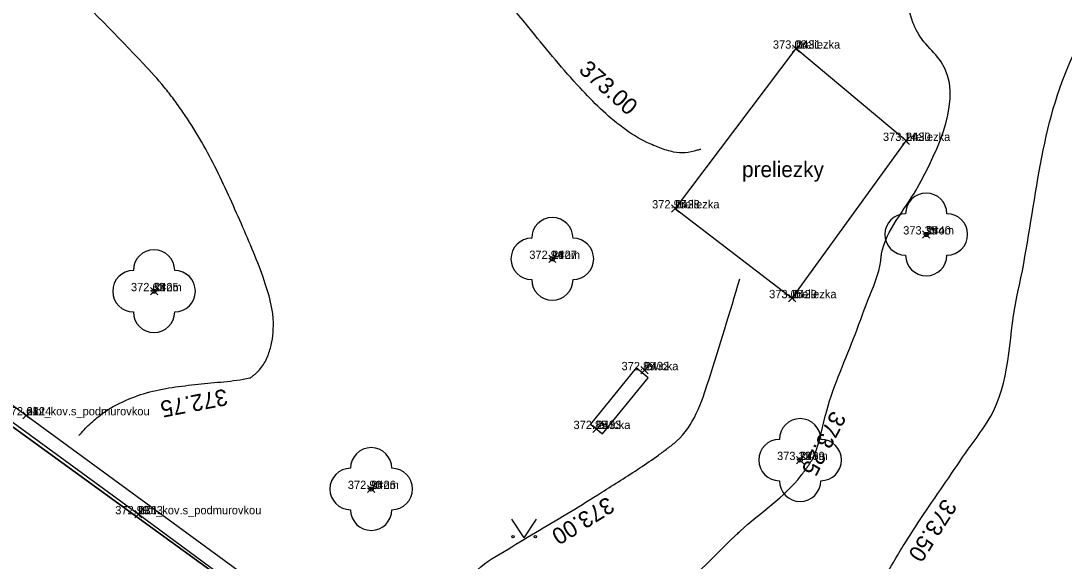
# Model space of a CAD drawing. Extents: x -400488 to -400124, y -1251493 to -1251223.
# Drawn here: x -400314.45 to -400289.23, y -1251383.58 to -1251370.53 of the extents above; entities that cross this region are included whole.
import ezdxf

# ---------------------------------------------------------------- set-up
doc = ezdxf.new("R2010")
doc.units = 0
for name, color, linetype in [('Level 20', 7, 'Continuous'), ('Level 21', 7, 'Continuous'), ('Level 22', 7, 'Continuous'), ('Level 23', 7, 'Continuous'), ('Level 31', 7, 'Continuous'), ('Level 35', 7, 'Continuous'), ('Level 36', 7, 'Continuous'), ('Level 49', 7, 'Continuous'), ('Level 60', 7, 'Continuous'), ('Level 63', 7, 'Continuous')]:
    doc.layers.add(name, color=color, linetype=linetype)

msp = doc.modelspace()

# ---------------------------------------------------------------- linework, layer by layer
at = {"layer": 'Level 20'}
for p, q in [((-400295.798, -1251371.288), (-400295.622, -1251371.112)), ((-400295.622, -1251371.288), (-400295.798, -1251371.112)), ((-400293.138, -1251373.518), (-400292.962, -1251373.342)), ((-400292.962, -1251373.518), (-400293.138, -1251373.342)), ((-400298.718, -1251375.148), (-400298.542, -1251374.972)), ((-400298.542, -1251375.148), (-400298.718, -1251374.972)), ((-400292.648, -1251375.778), (-400292.472, -1251375.602)), ((-400292.472, -1251375.778), (-400292.648, -1251375.602)), ((-400301.688, -1251376.368), (-400301.512, -1251376.192)), ((-400301.512, -1251376.368), (-400301.688, -1251376.192)), ((-400311.318, -1251377.148), (-400311.142, -1251376.972)), ((-400311.142, -1251377.148), (-400311.318, -1251376.972)), ((-400295.888, -1251377.318), (-400295.712, -1251377.142)), ((-400295.712, -1251377.318), (-400295.888, -1251377.142)), ((-400299.458, -1251379.058), (-400299.282, -1251378.882)), ((-400299.282, -1251379.058), (-400299.458, -1251378.882)), ((-400314.398, -1251380.148), (-400314.222, -1251379.972)), ((-400314.222, -1251380.148), (-400314.398, -1251379.972)), ((-400300.618, -1251380.478), (-400300.442, -1251380.302)), ((-400300.442, -1251380.478), (-400300.618, -1251380.302)), ((-400295.698, -1251381.228), (-400295.522, -1251381.052)), ((-400295.522, -1251381.228), (-400295.698, -1251381.052)), ((-400306.068, -1251381.928), (-400305.892, -1251381.752)), ((-400305.892, -1251381.928), (-400306.068, -1251381.752)), ((-400311.698, -1251382.538), (-400311.522, -1251382.362)), ((-400311.522, -1251382.538), (-400311.698, -1251382.362))]:
    msp.add_line(p, q, dxfattribs=at)
at = {"layer": 'Level 31'}
msp.add_lwpolyline([(-400295.71, -1251371.2), (-400298.63, -1251375.06), (-400295.8, -1251377.23), (-400293.05, -1251373.43), (-400295.71, -1251371.2)], dxfattribs=at)
at = {"layer": 'Level 35'}
for points in [[(-400330.938, -1251368.394), (-400330.78, -1251368.19), (-400329.16, -1251369.12), (-400314.31, -1251380.06), (-400302.65, -1251388.59)], [(-400279.37, -1251372.32), (-400292.97, -1251391.4), (-400293.356, -1251391.833), (-400293.82, -1251392.23), (-400294.281, -1251392.435), (-400294.92, -1251392.64), (-400295.666, -1251392.756), (-400296.53, -1251392.79), (-400297.13, -1251392.716), (-400297.73, -1251392.55), (-400298.17, -1251392.329), (-400298.61, -1251392.05), (-400311.61, -1251382.45), (-400320.06, -1251376.29)]]:
    msp.add_lwpolyline(points, dxfattribs=at)
at = {"layer": 'Level 36'}
for q in [(-400302.58, -1251382.572), (-400301.98, -1251382.572)]:
    msp.add_line((-400302.28, -1251383.022), q, dxfattribs=at)
for centre, radius in [((-400292.56, -1251375.69), 0.05), ((-400301.6, -1251376.28), 0.05), ((-400311.23, -1251377.06), 0.05), ((-400295.61, -1251381.14), 0.05), ((-400305.98, -1251381.84), 0.05), ((-400302.55, -1251382.992), 0.03), ((-400302.01, -1251382.992), 0.03)]:
    msp.add_circle(centre, radius, dxfattribs=at)
for centre, start, end in [((-400292.56, -1251375.19), 0, 180), ((-400293.06, -1251375.69), 90, 270), ((-400292.06, -1251375.69), 270, 90), ((-400301.6, -1251375.78), 0, 180), ((-400302.1, -1251376.28), 90, 270), ((-400301.1, -1251376.28), 270, 90), ((-400311.23, -1251376.56), 0, 180), ((-400292.56, -1251376.19), 180, 0), ((-400311.73, -1251377.06), 90, 270), ((-400310.73, -1251377.06), 270, 90), ((-400301.6, -1251376.78), 180, 0), ((-400311.23, -1251377.56), 180, 0), ((-400295.61, -1251380.64), 0, 180), ((-400296.11, -1251381.14), 90, 270), ((-400295.11, -1251381.14), 270, 90), ((-400305.98, -1251381.34), 0, 180), ((-400306.48, -1251381.84), 90, 270), ((-400305.48, -1251381.84), 270, 90), ((-400295.61, -1251381.64), 180, 0), ((-400305.98, -1251382.34), 180, 0)]:
    msp.add_arc(centre, 0.5, start, end, dxfattribs=at)
at = {"layer": 'Level 49'}
for points in [[(-400282.087, -1251375.169), (-400281.69, -1251370.822), (-400281.381, -1251368.586), (-400280.551, -1251363.9), (-400280.546, -1251363.886), (-400280.15, -1251362.887), (-400279.737, -1251361.896), (-400279.326, -1251360.9), (-400278.941, -1251359.886), (-400278.883, -1251359.562), (-400278.885, -1251359.094), (-400279.241, -1251356.971), (-400279.631, -1251356.354), (-400280.512, -1251355.223), (-400282.534, -1251353.186), (-400283.018, -1251352.792), (-400283.53, -1251352.437), (-400284.027, -1251352.07), (-400284.466, -1251351.641), (-400284.483, -1251351.618), (-400284.488, -1251351.612), (-400285.314, -1251350.99), (-400287.151, -1251349.31), (-400292.845, -1251345.168), (-400292.862, -1251345.159), (-400295.431, -1251343.95), (-400295.488, -1251343.921), (-400297.591, -1251342.594), (-400300.391, -1251340.357), (-400303.398, -1251337.509), (-400303.407, -1251337.499), (-400305.011, -1251335.906), (-400306.002, -1251335.061), (-400307.028, -1251334.259), (-400308.006, -1251333.512)], [(-400287.056, -1251382.036), (-400285.095, -1251371.378), (-400283.83, -1251364.736), (-400283.748, -1251364.223), (-400283.689, -1251363.872), (-400283.457, -1251363.276), (-400283.446, -1251363.218), (-400283.447, -1251363.211), (-400283.984, -1251359.342), (-400286.608, -1251354.299), (-400287.35, -1251353.443), (-400287.372, -1251353.421), (-400290.829, -1251350.218), (-400294.574, -1251347.519), (-400294.601, -1251347.503), (-400295.474, -1251347.083), (-400295.494, -1251347.073), (-400299.293, -1251344.638), (-400304.542, -1251340.608), (-400305.224, -1251339.982), (-400305.246, -1251339.958), (-400308.629, -1251336.24), (-400309.532, -1251335.395)], [(-400298.594, -1251390.918), (-400297.579, -1251389.803), (-400296.576, -1251388.675), (-400295.294, -1251386.973), (-400294.717, -1251386.031), (-400294.176, -1251385.068), (-400293.64, -1251384.103), (-400293.079, -1251383.154), (-400292.558, -1251382.354), (-400292.017, -1251381.567), (-400291.474, -1251380.779), (-400290.946, -1251379.978), (-400290.936, -1251379.958), (-400290.353, -1251377.108), (-400290.345, -1251377.073), (-400289.148, -1251371.673), (-400289.131, -1251371.633), (-400288.68, -1251369.757), (-400288.682, -1251369.751), (-400289.179, -1251365.184), (-400289.187, -1251365.045), (-400289.199, -1251364.086), (-400289.178, -1251363.127), (-400289.151, -1251362.167), (-400289.146, -1251361.208), (-400289.326, -1251359.947), (-400289.998, -1251358.61), (-400290.194, -1251358.383), (-400290.2, -1251358.378), (-400291.608, -1251356.855), (-400292.307, -1251356.088), (-400293.021, -1251355.336), (-400293.116, -1251355.24), (-400296.365, -1251351.788), (-400297.616, -1251350.178), (-400299.549, -1251347.891), (-400299.559, -1251347.877), (-400299.595, -1251347.847), (-400301.142, -1251346.859), (-400302.556, -1251345.879), (-400307.962, -1251342.189), (-400307.971, -1251342.179), (-400307.982, -1251342.152), (-400308.883, -1251340.471), (-400309.528, -1251339.56), (-400310.26, -1251338.706), (-400310.968, -1251337.837), (-400311.406, -1251337.164)], [(-400300.667, -1251389.478), (-400300.483, -1251388.773), (-400300.384, -1251388.062), (-400300.344, -1251387.35), (-400300.339, -1251386.641), (-400300.34, -1251386.636), (-400300.362, -1251386.605), (-400300.534, -1251386.354), (-400300.515, -1251385.99), (-400300.109, -1251385.615), (-400297.14, -1251382.932), (-400297.057, -1251382.855), (-400295.589, -1251381.52), (-400295.422, -1251381.289), (-400295.284, -1251381.059), (-400295.265, -1251381.015), (-400294.968, -1251379.948), (-400294.642, -1251379.013), (-400294.274, -1251378.09), (-400293.924, -1251377.161), (-400293.647, -1251376.207), (-400293.646, -1251376.19), (-400293.641, -1251376.158), (-400292.799, -1251374.602), (-400292.78, -1251374.568), (-400292.201, -1251371.517), (-400292.573, -1251371.086), (-400292.863, -1251370.616), (-400292.873, -1251370.59), (-400293.119, -1251369.55), (-400293.291, -1251368.49), (-400293.49, -1251367.439), (-400293.821, -1251366.425), (-400295.335, -1251363.46), (-400297.084, -1251360.63), (-400298.379, -1251358.699), (-400299.238, -1251357.272), (-400300.054, -1251355.818), (-400300.862, -1251354.357), (-400301.693, -1251352.905), (-400302.556, -1251351.775), (-400302.586, -1251351.768), (-400302.595, -1251351.766), (-400303.457, -1251351.41), (-400304.217, -1251350.882), (-400305.536, -1251349.48), (-400306.763, -1251347.91), (-400307.407, -1251347.171), (-400308.106, -1251346.519), (-400308.834, -1251345.958), (-400309.579, -1251345.414), (-400310.323, -1251344.863), (-400311.049, -1251344.285), (-400311.07, -1251344.262), (-400311.075, -1251344.251), (-400312.804, -1251340.258), (-400313.009, -1251339.843), (-400313.235, -1251339.439), (-400313.463, -1251339.034), (-400313.486, -1251338.992)], [(-400298.007, -1251373.633), (-400298.101, -1251373.657), (-400298.385, -1251373.715), (-400298.668, -1251373.698), (-400298.999, -1251373.598), (-400299.315, -1251373.468), (-400299.9, -1251373.106), (-400300.929, -1251372.15), (-400302.098, -1251370.777), (-400305.291, -1251366.626), (-400307.213, -1251363.775), (-400309.026, -1251360.802), (-400309.479, -1251359.989), (-400309.683, -1251359.57), (-400309.864, -1251359.138), (-400309.872, -1251359.107), (-400310.092, -1251357.753), (-400310.245, -1251356.389), (-400310.408, -1251355.025), (-400310.657, -1251353.672), (-400310.667, -1251353.649), (-400314.159, -1251348.989), (-400316.285, -1251346.155), (-400316.296, -1251346.134), (-400316.569, -1251345.318), (-400316.732, -1251344.464), (-400316.96, -1251343.625)], [(-400313.045, -1251380.55), (-400312.785, -1251380.273), (-400312.64, -1251380.146), (-400312.489, -1251380.025), (-400312.237, -1251379.858), (-400311.969, -1251379.724), (-400311.411, -1251379.516), (-400310.791, -1251379.385), (-400310.166, -1251379.309), (-400309.54, -1251379.247), (-400308.917, -1251379.155), (-400308.899, -1251379.15), (-400308.83, -1251379.101), (-400308.767, -1251379.048), (-400308.656, -1251378.931), (-400308.494, -1251378.661), (-400308.397, -1251378.361), (-400308.352, -1251378.054), (-400308.348, -1251377.725), (-400308.396, -1251377.399), (-400308.564, -1251376.806), (-400309.119, -1251375.433), (-400309.758, -1251374.051), (-400310.53, -1251372.737), (-400310.751, -1251372.429), (-400310.982, -1251372.131), (-400311.485, -1251371.569), (-400315.465, -1251367.634), (-400317.117, -1251365.966), (-400317.595, -1251365.311), (-400317.789, -1251364.95), (-400317.971, -1251364.582), (-400317.985, -1251364.548), (-400317.986, -1251364.544), (-400318.112, -1251363.714), (-400319.064, -1251357.286), (-400319.758, -1251356.341)], [(-400302.274, -1251388.348), (-400302.272, -1251388.271), (-400302.278, -1251388.233), (-400302.281, -1251388.228), (-400302.591, -1251387.772), (-400302.918, -1251387.325), (-400303.243, -1251386.879), (-400303.551, -1251386.426), (-400303.823, -1251385.744), (-400303.889, -1251385.388), (-400303.927, -1251385.033), (-400303.913, -1251384.678), (-400303.803, -1251384.323), (-400303.411, -1251383.791), (-400302.671, -1251383.29), (-400301.914, -1251382.832), (-400301.154, -1251382.385), (-400300.407, -1251381.918), (-400299.486, -1251381.332), (-400299.035, -1251381.021), (-400298.814, -1251380.857), (-400298.596, -1251380.685), (-400297.82, -1251379.213), (-400297.067, -1251376.761)]]:
    msp.add_spline(points, degree=3, dxfattribs=at)
at = {"layer": 'Level 60'}
msp.add_lwpolyline([(-400300.385, -1251380.508), (-400299.28, -1251379.151), (-400299.571, -1251378.914), (-400300.675, -1251380.272)], close=True, dxfattribs=at)
at = {"layer": 'Level 63'}
for p, q in [((-400298.43, -1251392.08), (-400336.35, -1251364.63)), ((-400336.35, -1251364.63), (-400298.43, -1251392.08))]:
    msp.add_line(p, q, dxfattribs=at)

# ---------------------------------------------------------------- texts
at = {"layer": 'Level 21'}
for s, p in [('2431', (-400295.71, -1251371.2)), ('2430', (-400293.05, -1251373.43)), ('2428', (-400298.63, -1251375.06)), ('2440', (-400292.56, -1251375.69)), ('2427', (-400301.6, -1251376.28)), ('2425', (-400311.23, -1251377.06)), ('2429', (-400295.8, -1251377.23)), ('2432', (-400299.37, -1251378.97)), ('2424', (-400314.31, -1251380.06)), ('2433', (-400300.53, -1251380.39)), ('2439', (-400295.61, -1251381.14)), ('2426', (-400305.98, -1251381.84)), ('2363', (-400311.61, -1251382.45))]:
    msp.add_text(s, height=0.2, dxfattribs=at).set_placement(p)
at = {"layer": 'Level 22'}
for s, p in [('preliezka', (-400295.71, -1251371.2)), ('preliezka', (-400293.05, -1251373.43)), ('preliezka', (-400298.63, -1251375.06)), ('strom', (-400292.56, -1251375.69)), ('strom', (-400301.6, -1251376.28)), ('strom', (-400311.23, -1251377.06)), ('preliezka', (-400295.8, -1251377.23)), ('lavicka', (-400299.37, -1251378.97)), ('plot_kov.s_podmurovkou', (-400314.31, -1251380.06)), ('lavicka', (-400300.53, -1251380.39)), ('strom', (-400295.61, -1251381.14)), ('strom', (-400305.98, -1251381.84)), ('plot_kov.s_podmurovkou', (-400311.61, -1251382.45))]:
    msp.add_text(s, height=0.2, dxfattribs=at).set_placement(p)
at = {"layer": 'Level 23'}
for s, p in [('373.08', (-400296.268, -1251371.2)), ('373.14', (-400293.608, -1251373.43)), ('372.95', (-400299.189, -1251375.06)), ('373.35', (-400293.119, -1251375.69)), ('372.94', (-400302.158, -1251376.28)), ('372.63', (-400311.788, -1251377.06)), ('373.05', (-400296.359, -1251377.23)), ('372.89', (-400299.928, -1251378.97)), ('372.61', (-400314.843, -1251380.06)), ('372.85', (-400301.089, -1251380.39)), ('373.23', (-400296.168, -1251381.14)), ('372.90', (-400306.546, -1251381.84)), ('372.99', (-400312.168, -1251382.45))]:
    msp.add_text(s, height=0.2, dxfattribs=at).set_placement(p)
at = {"layer": 'Level 31'}
msp.add_text('preliezky', height=0.375, dxfattribs=at).set_placement((-400297.013, -1251374.304))
at = {"layer": 'Level 49'}
for s, rotation, p in [('373.00', 318.1931, (-400300.984, -1251371.746)), ('372.75', 191.0042, (-400309.497, -1251379.414)), ('373.25', 242.6813, (-400294.836, -1251379.926)), ('373.00', 211.7797, (-400300.266, -1251382.009)), ('373.50', 237.5744, (-400292.134, -1251382.046))]:
    msp.add_text(s, height=0.4, rotation=rotation, dxfattribs=at).set_placement(p)

doc.saveas('drawing.dxf')
